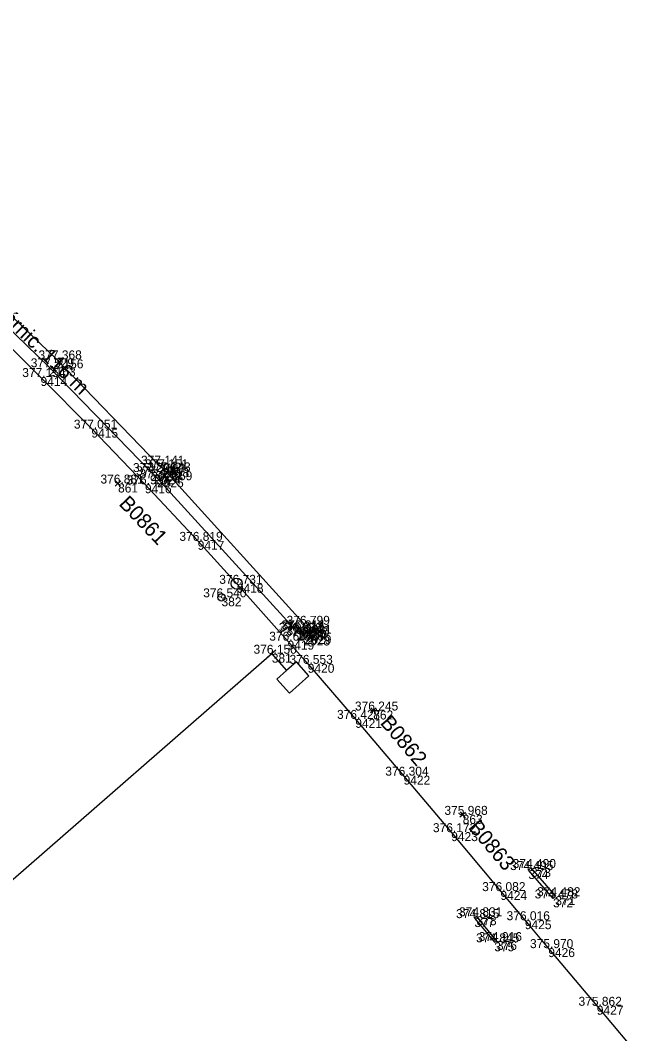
# Model space of a CAD drawing. Extents: x -599511 to -595511, y -1067427 to -1062061.
# Drawn here: x -596725.5 to -596641.9, y -1065474 to -1065338.2 of the extents above; entities that cross this region are included whole.
import ezdxf

# ---------------------------------------------------------------- set-up
doc = ezdxf.new("R2010")
doc.units = 0
for name, color, linetype in [('Vrstva 1', 7, 'Continuous'), ('Vrstva 14', 7, 'Continuous'), ('Vrstva 19', 7, 'Continuous'), ('Vrstva 60', 7, 'Continuous'), ('Vrstva 61', 7, 'Continuous'), ('Vrstva 7', 7, 'Continuous')]:
    doc.layers.add(name, color=color, linetype=linetype)

msp = doc.modelspace()

# ---------------------------------------------------------------- linework, layer by layer
at = {"layer": 'Vrstva 1'}
msp.add_lwpolyline([(-596729.29, -1065379.59), (-596722.75, -1065386.03), (-596715.93, -1065392.94), (-596708.76, -1065400.4), (-596701.69, -1065407.98), (-596696.44, -1065413.74), (-596689.65, -1065421.36), (-596686.94, -1065424.46), (-596680.57, -1065431.84), (-596674.1, -1065439.45), (-596667.72, -1065447.02), (-596661.12, -1065454.92), (-596657.85, -1065458.82), (-596654.71, -1065462.56), (-596648.21, -1065470.29), (-596641.92, -1065477.78)], dxfattribs=at)
at = {"layer": 'Vrstva 14'}
msp.add_lwpolyline([(-596688.36, -1065420.16), (-596688.18, -1065420.03), (-596687.53, -1065420.8), (-596687.34, -1065420.62), (-596688.01, -1065419.84), (-596687.33, -1065419.23), (-596705.98, -1065398.67), (-596706.41, -1065398.26), (-596706.92, -1065397.78), (-596720.57, -1065383.66), (-596734.27, -1065370.54), (-596749.34, -1065356.72), (-596763.3, -1065344.44), (-596770.84, -1065338.22), (-596771.74, -1065339.2), (-596764.28, -1065345.51), (-596750.22, -1065357.72), (-596735.21, -1065371.52), (-596721.61, -1065384.72), (-596707.91, -1065398.76), (-596707.49, -1065399.19), (-596707.13, -1065399.59), (-596688.36, -1065420.16)], dxfattribs=at)
at = {"layer": 'Vrstva 19'}
for points in [[(-596657.37, -1065452.1), (-596657.03, -1065451.82), (-596653.76, -1065455.6), (-596654.07, -1065455.9)], [(-596661.94, -1065461.78), (-596661.59, -1065461.61), (-596664.32, -1065458.29), (-596664.61, -1065458.54)]]:
    msp.add_lwpolyline(points, close=True, dxfattribs=at)
at = {"layer": 'Vrstva 60'}
for p, q in [((-596720.57, -1065383.66), (-596720.57, -1065383.66)), ((-596721.61, -1065384.72), (-596721.61, -1065384.72)), ((-596722.75, -1065386.03), (-596722.75, -1065386.03)), ((-596715.93, -1065392.94), (-596715.93, -1065392.94)), ((-596706.92, -1065397.78), (-596706.92, -1065397.78)), ((-596707.91, -1065398.76), (-596707.91, -1065398.76)), ((-596707.49, -1065399.19), (-596707.49, -1065399.19)), ((-596706.41, -1065398.26), (-596706.41, -1065398.26)), ((-596705.98, -1065398.67), (-596705.98, -1065398.67)), ((-596712.36, -1065400.3), (-596712.36, -1065400.3)), ((-596708.76, -1065400.4), (-596708.76, -1065400.4)), ((-596707.13, -1065399.59), (-596707.13, -1065399.59)), ((-596701.69, -1065407.98), (-596701.69, -1065407.98)), ((-596696.44, -1065413.74), (-596696.44, -1065413.74)), ((-596698.5, -1065415.55), (-596698.5, -1065415.55)), ((-596687.33, -1065419.23), (-596687.33, -1065419.23)), ((-596688.36, -1065420.16), (-596688.36, -1065420.16)), ((-596688.18, -1065420.03), (-596688.18, -1065420.03)), ((-596688.01, -1065419.84), (-596688.01, -1065419.84)), ((-596687.53, -1065420.8), (-596687.53, -1065420.8)), ((-596687.34, -1065420.62), (-596687.34, -1065420.62)), ((-596689.65, -1065421.36), (-596689.65, -1065421.36)), ((-596691.76, -1065423.11), (-596691.76, -1065423.11)), ((-596686.94, -1065424.46), (-596686.94, -1065424.46)), ((-596678.17, -1065430.72), (-596678.17, -1065430.72)), ((-596680.57, -1065431.84), (-596680.57, -1065431.84)), ((-596674.1, -1065439.45), (-596674.1, -1065439.45)), ((-596666.18, -1065444.7), (-596666.18, -1065444.7)), ((-596667.72, -1065447.02), (-596667.72, -1065447.02)), ((-596657.37, -1065452.1), (-596657.37, -1065452.1)), ((-596657.03, -1065451.82), (-596657.03, -1065451.82)), ((-596661.12, -1065454.92), (-596661.12, -1065454.92)), ((-596654.07, -1065455.9), (-596654.07, -1065455.9)), ((-596653.76, -1065455.6), (-596653.76, -1065455.6)), ((-596664.61, -1065458.54), (-596664.61, -1065458.54)), ((-596664.32, -1065458.29), (-596664.32, -1065458.29)), ((-596657.85, -1065458.82), (-596657.85, -1065458.82)), ((-596661.59, -1065461.61), (-596661.59, -1065461.61)), ((-596661.94, -1065461.78), (-596661.94, -1065461.78)), ((-596654.71, -1065462.56), (-596654.71, -1065462.56)), ((-596648.21, -1065470.29), (-596648.21, -1065470.29))]:
    msp.add_line(p, q, dxfattribs=at)
at = {"layer": 'Vrstva 7'}
for p, q in [((-596712, -1065399.96), (-596712.73, -1065400.65)), ((-596712.71, -1065399.94), (-596712.02, -1065400.66)), ((-596698.54, -1065415.51), (-596698.47, -1065415.59)), ((-596691.76, -1065423.11), (-596741.47, -1065466.46)), ((-596691.2, -1065422.61), (-596692.32, -1065423.61)), ((-596677.79, -1065430.39), (-596678.55, -1065431.04)), ((-596678.49, -1065430.34), (-596677.84, -1065431.1)), ((-596665.8, -1065444.37), (-596666.56, -1065445.02)), ((-596666.5, -1065444.31), (-596665.86, -1065445.08))]:
    msp.add_line(p, q, dxfattribs=at)
msp.add_lwpolyline([(-596691.76, -1065423.11), (-596689.77, -1065425.35), (-596691.07, -1065426.52), (-596689.41, -1065428.38), (-596686.8, -1065426.06), (-596688.46, -1065424.19), (-596689.77, -1065425.35)], dxfattribs=at)
for centre, radius in [((-596696.47, -1065413.71), 0.75), ((-596698.5, -1065415.55), 0.5)]:
    msp.add_circle(centre, radius, dxfattribs=at)

# ---------------------------------------------------------------- texts
at = {"layer": 'Vrstva 14'}
msp.add_text('nást. tvárnic. 116 m', height=2, rotation=315.8636, dxfattribs=at).set_placement((-596734.15, -1065372.31))
at = {"layer": 'Vrstva 60'}
for s, p in [('2156', (-596720.57, -1065384.86)), ('2163', (-596721.61, -1065385.92)), ('9414', (-596722.75, -1065387.23)), ('9415', (-596715.93, -1065394.14)), ('2157', (-596706.92, -1065398.98)), ('2023', (-596707.91, -1065399.96)), ('2024', (-596707.49, -1065400.39)), ('2158', (-596706.41, -1065399.46)), ('2159', (-596705.98, -1065399.86)), ('861', (-596712.36, -1065401.5)), ('9416', (-596708.76, -1065401.6)), ('2025', (-596707.13, -1065400.79)), ('9417', (-596701.69, -1065409.18)), ('9418', (-596696.44, -1065414.94)), ('382', (-596698.5, -1065416.75)), ('2031', (-596687.33, -1065420.43)), ('2026', (-596688.36, -1065421.35)), ('2027', (-596688.18, -1065421.23)), ('2030', (-596688.01, -1065421.04)), ('2028', (-596687.53, -1065422)), ('2029', (-596687.34, -1065421.82)), ('9419', (-596689.65, -1065422.56)), ('381', (-596691.76, -1065424.31)), ('9420', (-596686.94, -1065425.66)), ('9421', (-596680.57, -1065433.04)), ('862', (-596678.17, -1065431.92)), ('9422', (-596674.1, -1065440.65)), ('863', (-596666.18, -1065445.9)), ('9423', (-596667.72, -1065448.22)), ('374', (-596657.37, -1065453.3)), ('373', (-596657.03, -1065453.02)), ('9424', (-596661.12, -1065456.11)), ('372', (-596654.07, -1065457.1)), ('371', (-596653.76, -1065456.8)), ('377', (-596664.61, -1065459.74)), ('378', (-596664.32, -1065459.49)), ('9425', (-596657.85, -1065460.02)), ('376', (-596661.59, -1065462.81)), ('375', (-596661.94, -1065462.98)), ('9426', (-596654.71, -1065463.76)), ('9427', (-596648.21, -1065471.49))]:
    msp.add_text(s, height=1.2, dxfattribs=at).set_placement(p)
at = {"layer": 'Vrstva 61'}
for s, p in [('377.368', (-596723.02, -1065383.66)), ('377.529', (-596724.06, -1065384.72)), ('377.154', (-596725.2, -1065386.03)), ('377.051', (-596718.28, -1065392.94)), ('377.296', (-596710.36, -1065398.76)), ('377.141', (-596709.28, -1065397.78)), ('377.151', (-596708.77, -1065398.26)), ('377.143', (-596708.43, -1065398.67)), ('376.881', (-596714.72, -1065400.3)), ('376.934', (-596711.21, -1065400.4)), ('377.303', (-596709.94, -1065399.19)), ('377.291', (-596709.49, -1065399.59)), ('376.819', (-596704.14, -1065407.98)), ('376.731', (-596698.8, -1065413.74)), ('376.540', (-596700.95, -1065415.55)), ('376.799', (-596689.78, -1065419.23)), ('376.939', (-596690.82, -1065420.16)), ('376.812', (-596690.63, -1065420.03)), ('376.814', (-596690.46, -1065419.84)), ('376.677', (-596689.98, -1065420.8)), ('376.653', (-596689.79, -1065420.62)), ('376.607', (-596692.1, -1065421.36)), ('376.150', (-596694.21, -1065423.11)), ('376.553', (-596689.39, -1065424.46)), ('376.245', (-596680.62, -1065430.72)), ('376.427', (-596683.02, -1065431.84)), ('376.304', (-596676.55, -1065439.45)), ('375.968', (-596668.63, -1065444.7)), ('376.172', (-596670.17, -1065447.02)), ('374.490', (-596659.48, -1065451.82)), ('374.495', (-596659.83, -1065452.1)), ('376.082', (-596663.57, -1065454.92)), ('374.478', (-596656.53, -1065455.9)), ('374.482', (-596656.21, -1065455.6)), ('374.815', (-596667.07, -1065458.54)), ('374.831', (-596666.67, -1065458.29)), ('376.016', (-596660.3, -1065458.82)), ('374.845', (-596664.39, -1065461.78)), ('374.916', (-596664.04, -1065461.61)), ('375.970', (-596657.16, -1065462.56)), ('375.862', (-596650.66, -1065470.29))]:
    msp.add_text(s, height=1.2, dxfattribs=at).set_placement(p)
at = {"layer": 'Vrstva 7'}
for s, rotation, p in [('B0861', 313.8333, (-596712.36, -1065403.11)), ('B0862', 310.4004, (-596677.33, -1065432.43)), ('B0863', 310.0923, (-596665.52, -1065446.44))]:
    msp.add_text(s, height=2, rotation=rotation, dxfattribs=at).set_placement(p)

doc.saveas('drawing.dxf')
